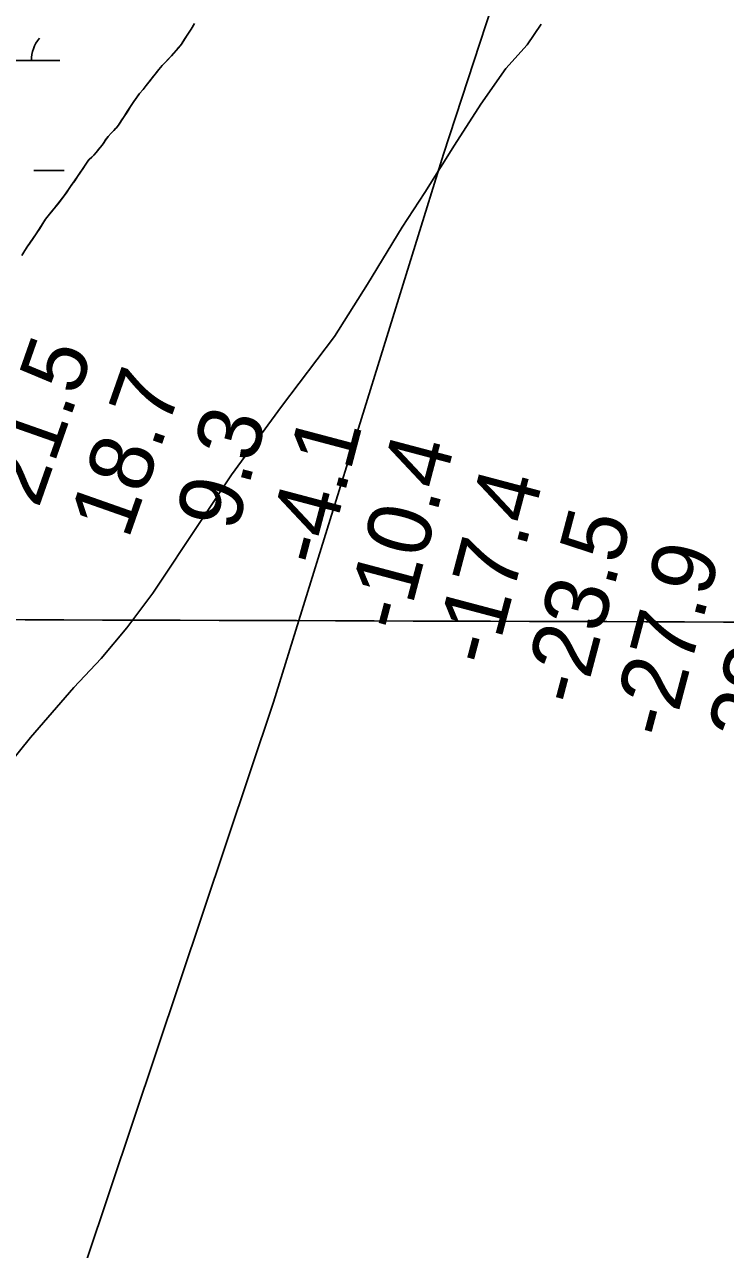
# Model space of a CAD drawing. Extents: x 3148686 to 3186545, y 916144 to 941516.
# Drawn here: x 3161772 to 3162509, y 932988 to 934275 of the extents above; entities that cross this region are included whole.
import ezdxf

# ---------------------------------------------------------------- set-up
doc = ezdxf.new("R2010")
doc.units = 0
for name, color, linetype in [('V-GRID-MAJR', 7, 'Continuous'), ('V-RIVR-EDGE', 7, 'Continuous'), ('V-RIVR-RANG', 7, 'Continuous'), ('V-SITE-VEGE', 7, 'Continuous'), ('V-TOPO-BNDY', 7, 'Continuous'), ('V-WETL-SWMP', 7, 'Continuous')]:
    doc.layers.add(name, color=color, linetype=linetype)

msp = doc.modelspace()

# ---------------------------------------------------------------- linework, layer by layer
at = {"layer": 'V-GRID-MAJR'}
msp.add_spline([(3152965.6, 933679.7), (3155575.1, 933670.5), (3160794.2, 933652.6), (3166013.2, 933635.6), (3171232.3, 933619.2), (3176451.4, 933603.7), (3181670.5, 933588.9), (3184280, 933581.8)], degree=3, dxfattribs=at)
at = {"layer": 'V-RIVR-EDGE'}
for points in [[(3162315.1, 934275.1), (3162300.5, 934253.2), (3162278.1, 934228.4), (3162251.7, 934190.9), (3162224, 934147.7), (3162193, 934098.1), (3162169.1, 934061.7), (3162132.5, 934001.8), (3162097.9, 933947), (3162042.4, 933873.3), (3161989.8, 933801.5), (3161957.8, 933753.7), (3161906.9, 933677.2), (3161879.8, 933640.8), (3161852.8, 933608.6)], [(3161852.8, 933608.6), (3161824, 933578.2), (3161778.5, 933525.8), (3161742.2, 933480.8), (3161690.6, 933412.2), (3161674.6, 933378.2), (3161660.3, 933363.7), (3161645.5, 933365.1), (3161638.4, 933376.1), (3161625.6, 933367.7), (3161609.2, 933337.6), (3161601.3, 933303.2), (3161582.5, 933289.4), (3161571.2, 933287.7), (3161534.2, 933236.7), (3161490.8, 933192.1), (3161455.6, 933159.9), (3161428.2, 933119.2), (3161404, 933081.7), (3161397.5, 933057.6), (3161401.8, 933043.4), (3161408.1, 933026.7), (3161404.2, 933009.4), (3161385.7, 932978.6)]]:
    msp.add_lwpolyline(points, dxfattribs=at)
at = {"layer": 'V-SITE-VEGE'}
for p, q in [((3161947.4, 934269.6), (3161950.8, 934275.5)), ((3161937, 934254), (3161943, 934263.3)), ((3161943, 934263.3), (3161947.4, 934269.6)), ((3161926.7, 934241.7), (3161934, 934250.2)), ((3161934, 934250.2), (3161937, 934254)), ((3161916.9, 934231.6), (3161926.7, 934241.7)), ((3161900.2, 934210.7), (3161913.5, 934227.5)), ((3161913.5, 934227.5), (3161916.9, 934231.6)), ((3161896.8, 934206.2), (3161900.2, 934210.7)), ((3161887.1, 934193.8), (3161893.2, 934202)), ((3161893.2, 934202), (3161896.8, 934206.2)), ((3161879.9, 934182.7), (3161883.5, 934188.4)), ((3161883.5, 934188.4), (3161887.1, 934193.8)), ((3161871, 934169), (3161877, 934178)), ((3161877, 934178), (3161879.9, 934182.7)), ((3161860.2, 934157), (3161863.1, 934160.5)), ((3161863.1, 934160.5), (3161864.6, 934161.9)), ((3161864.6, 934161.9), (3161866.1, 934163.2)), ((3161866.1, 934163.2), (3161867.5, 934164.8)), ((3161867.5, 934164.8), (3161868.4, 934165.7)), ((3161868.4, 934165.7), (3161871, 934169)), ((3161847.6, 934140.2), (3161851.8, 934145.5)), ((3161851.8, 934145.5), (3161853.7, 934147.8)), ((3161853.7, 934147.8), (3161855.8, 934151)), ((3161855.8, 934151), (3161857.3, 934153.3)), ((3161857.3, 934153.3), (3161860.2, 934157)), ((3161837.9, 934130), (3161839.5, 934132)), ((3161839.5, 934132), (3161840.2, 934132.7)), ((3161840.2, 934132.7), (3161845.2, 934137.5)), ((3161845.2, 934137.5), (3161847.6, 934140.2)), ((3161828, 934114.9), (3161836.1, 934127)), ((3161836.1, 934127), (3161837.9, 934130)), ((3161819.8, 934103.3), (3161828, 934114.9)), ((3161809.7, 934089.5), (3161816, 934097.6)), ((3161816, 934097.6), (3161819.8, 934103.3)), ((3161800.5, 934077.7), (3161803.4, 934081.3)), ((3161803.4, 934081.3), (3161809.7, 934089.5)), ((3161784.4, 934054.7), (3161794.3, 934070)), ((3161794.3, 934070), (3161798.5, 934075.3)), ((3161798.5, 934075.3), (3161800.5, 934077.7)), ((3161775.1, 934041.2), (3161784.4, 934054.7)), ((3161771.7, 934035.8), (3161772.6, 934037.1)), ((3161772.6, 934037.1), (3161774, 934039.4)), ((3161774, 934039.4), (3161775.1, 934041.2))]:
    msp.add_line(p, q, dxfattribs=at)
at = {"layer": 'V-TOPO-BNDY'}
msp.add_lwpolyline([(3161812.5, 932901.9), (3162033.7, 933562.9), (3162212.6, 934138.3), (3162378.7, 934645.9), (3162508, 935040.8), (3162683.8, 935537.4), (3162840, 935885), (3162914.5, 936083.1), (3162923, 936106.3), (3162974.7, 936290), (3163048.5, 936619.7), (3163067, 936827.2), (3163076.6, 937005.3), (3163062.3, 937127.3), (3163042.1, 937333.1)], dxfattribs=at)
at = {"layer": 'V-WETL-SWMP'}
for p, q in [((3161709.4, 934236.8), (3161809.4, 934236.7)), ((3161781.9, 934121.2), (3161813.9, 934121.2))]:
    msp.add_line(p, q, dxfattribs=at)
msp.add_lwpolyline([(3161769.2, 934032.1), (3161772.6, 934037.2), (3161775.1, 934041.2), (3161777.6, 934044.8), (3161780.9, 934049.6), (3161784.4, 934054.7), (3161788.2, 934060.4), (3161791.4, 934065.6), (3161794.3, 934070), (3161798.4, 934075.3), (3161801.3, 934078.8), (3161803.4, 934081.3), (3161807.1, 934086), (3161811.6, 934091.8), (3161816, 934097.7), (3161819.7, 934103.3), (3161822, 934106.5), (3161824.9, 934110.5), (3161828, 934114.9), (3161831.1, 934119.6), (3161833.4, 934123.1), (3161836.1, 934127), (3161837.9, 934130), (3161840.2, 934132.8), (3161842.8, 934135.3), (3161845.2, 934137.5), (3161847.6, 934140.2), (3161849.7, 934142.9), (3161851.7, 934145.5), (3161853.7, 934147.8), (3161855.4, 934150.3), (3161857.2, 934153.2), (3161860.2, 934157), (3161863.1, 934160.5), (3161866.1, 934163.2), (3161868.3, 934165.7), (3161871, 934169), (3161873.9, 934173.3), (3161877, 934178), (3161880.1, 934183.1), (3161883.5, 934188.4), (3161887.1, 934193.8), (3161889.9, 934197.7), (3161893.2, 934202), (3161896.8, 934206.3), (3161900.2, 934210.7), (3161904.5, 934216.1), (3161906.4, 934218.5), (3161910.8, 934224.2), (3161913.5, 934227.5), (3161917, 934231.6), (3161921.7, 934236.5), (3161926.7, 934241.7), (3161928.7, 934244), (3161931.8, 934247.7), (3161934, 934250.3), (3161937, 934254.1), (3161938.7, 934256.5), (3161941.2, 934260.4), (3161943, 934263.3), (3161947.3, 934269.6), (3161950.8, 934275.5)], dxfattribs=at)
msp.add_arc((3161814.6, 934237.1), 35.2, 139.1678, 180.7115, dxfattribs=at)

# ---------------------------------------------------------------- texts
at = {"layer": 'V-RIVR-RANG'}
for s, rotation, p in [('21.5', 70.6283, (3161786.7, 933765.4)), ('18.7', 70.6283, (3161881.1, 933732.5)), ('9.3', 75.1814, (3161995, 933740.4)), ('-4.1', 75.1814, (3162087.8, 933703.1)), ('-10.4', 75.1814, (3162172.1, 933634.6)), ('-17.4', 75.1814, (3162265.1, 933598.3)), ('-23.5', 75.1814, (3162358.4, 933556.6)), ('-27.9', 75.1814, (3162451.7, 933522.1)), ('-23.3', 75.1814, (3162546, 933486.7))]:
    msp.add_text(s, height=67, rotation=rotation, dxfattribs=at).set_placement(p)

doc.saveas('drawing.dxf')
